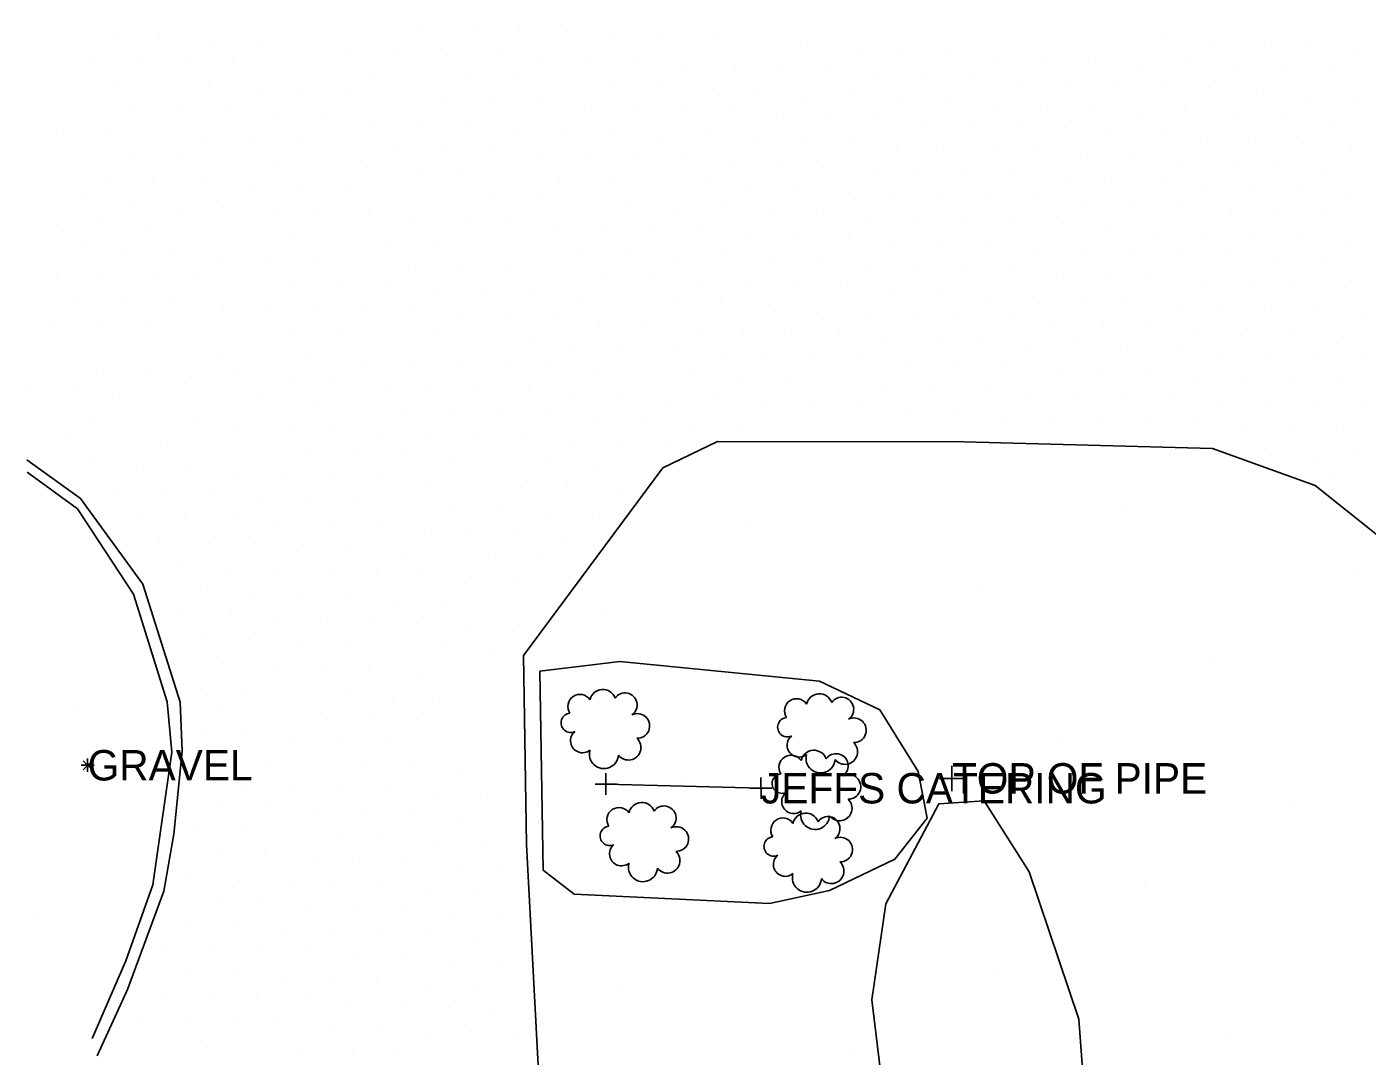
# Model space of a CAD drawing. Extents: x 1733582 to 1734070, y 467256 to 468256.
# Drawn here: x 1733724.1 to 1733803.5, y 467494.6 to 467555.6 of the extents above; entities that cross this region are included whole.
import ezdxf

# ---------------------------------------------------------------- set-up
doc = ezdxf.new("R2010")
doc.units = 0
for name, color, linetype in [('Default', 7, 'Continuous'), ('S_Curb_Type_3', 7, 'Continuous'), ('S_Drainage_Invert_Culvert', 7, 'Continuous'), ('S_Ground_SpotElevation', 7, 'Continuous'), ('S_Misc_MiscItems', 7, 'Continuous'), ('S_Property_Garden', 7, 'Continuous'), ('S_Roadway_Drive_Paved', 7, 'Continuous'), ('S_Survey_Shot', 7, 'Continuous'), ('S_Text', 7, 'Continuous'), ('S_Traffic_Sign_DoublePost', 7, 'Continuous'), ('S_Trees_Bush', 7, 'Continuous'), ('S_Trees_Bush_Line', 7, 'Continuous')]:
    doc.layers.add(name, color=color, linetype=linetype)

# ---------------------------------------------------------------- blocks, each defined once
blk = doc.blocks.new('POINT_DISPLAY')
at = {"layer": 'Default'}
blk.add_line((0, 0), (0, 0), dxfattribs=at)

msp = doc.modelspace()

# ---------------------------------------------------------------- linework, layer by layer
at = {"layer": 'S_Curb_Type_3'}
msp.add_lwpolyline([(1733724.139, 467529.217), (1733727.119, 467527.047), (1733730.432, 467522.001), (1733732.42, 467515.62), (1733732.714, 467512.654), (1733731.587, 467504.798), (1733729.979, 467500.29), (1733727.98, 467495.687)], dxfattribs=at)
at = {"layer": 'S_Drainage_Invert_Culvert'}
for p, q in [((1733778.9, 467511.846), (1733778.9, 467510.346)), ((1733778.15, 467511.096), (1733779.65, 467511.096))]:
    msp.add_line(p, q, dxfattribs=at)
at = {"layer": 'S_Misc_MiscItems'}
for p, q in [((1733727.982, 467511.608), (1733727.458, 467512.132)), ((1733727.982, 467512.132), (1733727.458, 467511.608)), ((1733727.72, 467512.263), (1733727.72, 467511.477)), ((1733728.113, 467511.87), (1733727.327, 467511.87))]:
    msp.add_line(p, q, dxfattribs=at)
at = {"layer": 'S_Property_Garden'}
msp.add_lwpolyline([(1733756.524, 467504.241), (1733754.694, 467505.659), (1733754.495, 467517.433), (1733759.233, 467518.012), (1733771.049, 467516.839), (1733774.623, 467515.157), (1733776.898, 467511.492), (1733777.426, 467508.736), (1733775.526, 467506.318), (1733771.64, 467504.466), (1733768.086, 467503.694), (1733756.524, 467504.241)], dxfattribs=at)
at = {"layer": 'S_Roadway_Drive_Paved'}
for points in [[(1733811.739, 467519.514), (1733806.075, 467523.904), (1733800.413, 467528.442), (1733794.32, 467530.63), (1733779.611, 467531.008), (1733765.012, 467531.03), (1733761.779, 467529.481), (1733753.522, 467518.374), (1733753.708, 467507.172), (1733754.671, 467488.867), (1733755.589, 467445.891), (1733749.43, 467445.76)], [(1733728.284, 467494.674), (1733730.081, 467498.603), (1733732.23, 467504.412), (1733732.833, 467507.798), (1733733.323, 467512.698), (1733733.207, 467515.602), (1733730.979, 467522.589), (1733727.293, 467527.659), (1733724.118, 467529.953)]]:
    msp.add_lwpolyline(points, dxfattribs=at)
at = {"layer": 'S_Survey_Shot'}
for p, q in [((1733758.408, 467510.123), (1733758.406, 467511.395)), ((1733757.771, 467510.758), (1733759.043, 467510.76)), ((1733758.407, 467510.759), (1733758.407, 467510.759)), ((1733766.956, 467510.509), (1733768.228, 467510.511)), ((1733767.593, 467509.874), (1733767.591, 467511.146)), ((1733767.592, 467510.51), (1733767.592, 467510.51))]:
    msp.add_line(p, q, dxfattribs=at)
at = {"layer": 'S_Traffic_Sign_DoublePost'}
msp.add_lwpolyline([(1733767.592, 467510.51), (1733758.407, 467510.759)], dxfattribs=at)
at = {"layer": 'S_Trees_Bush'}
for centre, radius, start, end in [((1733756.871, 467515.35), 0.716, 33.64054, 213.59091), ((1733758.224, 467515.585), 0.774, 19.72769, 168.00323), ((1733759.54, 467515.44), 0.714, 304.7168, 145.28321), ((1733771.05, 467515.328), 0.774, 19.72769, 168.00323), ((1733769.697, 467515.093), 0.716, 33.64054, 213.59091), ((1733772.366, 467515.183), 0.714, 304.7168, 145.28321), ((1733756.327, 467514.382), 0.575, 95.18751, 295.46148), ((1733760.267, 467514.196), 0.731, 268.12197, 116.01721), ((1733769.153, 467514.125), 0.575, 95.18751, 295.46148), ((1733773.093, 467513.939), 0.731, 268.12197, 116.01721), ((1733757.019, 467513.316), 0.705, 129.15555, 309.41051), ((1733759.743, 467512.92), 0.74, 216.98087, 47.49649), ((1733769.845, 467513.059), 0.705, 129.15555, 309.41051), ((1733772.569, 467512.663), 0.74, 216.98087, 47.49649), ((1733758.293, 467512.531), 0.861, 163.74266, 356.27601), ((1733769.372, 467511.751), 0.716, 33.64054, 213.59091), ((1733770.725, 467511.986), 0.774, 19.72769, 168.00323), ((1733771.119, 467512.274), 0.861, 163.74266, 356.27601), ((1733772.041, 467511.841), 0.714, 304.7168, 145.28321), ((1733768.828, 467510.783), 0.575, 95.18751, 295.46148), ((1733772.768, 467510.597), 0.731, 268.12197, 116.01721), ((1733760.534, 467508.891), 0.774, 19.72769, 168.00323), ((1733769.52, 467509.717), 0.705, 129.15555, 309.41051), ((1733772.244, 467509.321), 0.74, 216.98087, 47.49649), ((1733759.181, 467508.656), 0.716, 33.64054, 213.59091), ((1733761.85, 467508.746), 0.714, 304.7168, 145.28321), ((1733770.239, 467508.268), 0.774, 19.72769, 168.00323), ((1733770.794, 467508.932), 0.861, 163.74266, 356.27601), ((1733758.637, 467507.688), 0.575, 95.18751, 295.46148), ((1733762.577, 467507.502), 0.731, 268.12197, 116.01721), ((1733768.886, 467508.033), 0.716, 33.64054, 213.59091), ((1733771.555, 467508.123), 0.714, 304.7168, 145.28321), ((1733768.342, 467507.065), 0.575, 95.18751, 295.46148), ((1733772.282, 467506.879), 0.731, 268.12197, 116.01721), ((1733759.329, 467506.622), 0.705, 129.15555, 309.41051), ((1733762.053, 467506.226), 0.74, 216.98087, 47.49649), ((1733769.034, 467505.999), 0.705, 129.15555, 309.41051), ((1733760.603, 467505.837), 0.861, 163.74266, 356.27601), ((1733771.758, 467505.603), 0.74, 216.98087, 47.49649), ((1733770.308, 467505.214), 0.861, 163.74266, 356.27601)]:
    msp.add_arc(centre, radius, start, end, dxfattribs=at)
at = {"layer": 'S_Trees_Bush_Line'}
msp.add_lwpolyline([(1733757.132, 467425.823), (1733762.294, 467426.816), (1733768.302, 467429.336), (1733775.509, 467433.305), (1733779.429, 467440.16), (1733780.117, 467448.929), (1733774.149, 467497.977), (1733774.984, 467503.667), (1733778.123, 467509.595), (1733780.8, 467509.768), (1733783.475, 467505.563), (1733786.412, 467496.844), (1733790.523, 467441.256), (1733794.187, 467436.042), (1733797.957, 467433.37), (1733800.467, 467407.761), (1733803.443, 467377.812)], dxfattribs=at)

# ---------------------------------------------------------------- block references
at = {"layer": 'S_Ground_SpotElevation'}
for p in [(1733729.413, 467555.09), (1733747.567, 467555.559), (1733750.577, 467555.586), (1733753.304, 467555.377), (1733756.124, 467555.31), (1733758.919, 467555.005), (1733731.999, 467554.884), (1733734.853, 467554.669), (1733737.842, 467554.527), (1733743.246, 467554.324), (1733746.106, 467554.122), (1733761.739, 467554.845), (1733764.785, 467554.842), (1733770.328, 467554.514), (1733773.263, 467554.191), (1733791.441, 467554.845), (1733794.262, 467554.612), (1733797.376, 467554.538), (1733800.106, 467554.378), (1733802.952, 467554.242), (1733727.938, 467553.829), (1733730.657, 467553.441), (1733733.579, 467553.536), (1733736.271, 467553.445), (1733749.044, 467553.904), (1733751.977, 467553.884), (1733754.653, 467553.667), (1733757.443, 467553.684), (1733760.254, 467553.489), (1733763.19, 467553.312), (1733775.911, 467554.035), (1733778.646, 467554.085), (1733781.617, 467553.798), (1733784.393, 467553.843), (1733787.393, 467553.6), (1733789.964, 467553.37), (1733792.854, 467553.469), (1733744.693, 467552.724), (1733750.441, 467552.762), (1733753.237, 467552.576), (1733766.065, 467553.289), (1733768.69, 467553.224), (1733771.62, 467553.077), (1733774.355, 467552.905), (1733777.403, 467552.883), (1733780.087, 467552.574), (1733795.657, 467553.143), (1733798.402, 467553.049), (1733801.234, 467552.913), (1733729.171, 467552.277), (1733734.879, 467552.043), (1733758.928, 467552.054), (1733761.54, 467552.097), (1733764.713, 467551.961), (1733767.472, 467551.848), (1733782.905, 467552.322), (1733785.907, 467552.25), (1733788.597, 467552.198), (1733791.455, 467552.177), (1733794.116, 467551.966), (1733796.945, 467551.737), (1733737.699, 467551.649), (1733740.38, 467551.671), (1733743.236, 467551.5), (1733748.75, 467551.262), (1733751.744, 467551.079), (1733754.591, 467551.072), (1733770.182, 467551.446), (1733772.859, 467551.541), (1733775.691, 467551.429), (1733778.54, 467551.17), (1733781.6, 467550.953), (1733799.868, 467551.425), (1733802.69, 467551.288), (1733730.374, 467550.793), (1733733.252, 467550.692), (1733736.036, 467550.559), (1733738.815, 467550.332), (1733741.942, 467550.218), (1733757.574, 467550.78), (1733760.321, 467550.646), (1733762.96, 467550.595), (1733765.841, 467550.625), (1733768.528, 467550.331), (1733771.403, 467550.191), (1733774.283, 467550.123), (1733784.164, 467550.809), (1733787.077, 467550.828), (1733789.947, 467550.487), (1733792.665, 467550.638), (1733795.768, 467550.437), (1733798.579, 467550.308), (1733726.306, 467549.413), (1733728.868, 467549.374), (1733744.519, 467549.914), (1733747.416, 467550.027), (1733750.091, 467549.881), (1733753.008, 467549.481), (1733755.958, 467549.334), (1733777.183, 467549.777), (1733779.993, 467549.866), (1733782.772, 467549.684), (1733785.537, 467549.602), (1733791.283, 467549.363), (1733801.311, 467550.038), (1733734.513, 467549.042), (1733737.32, 467549.112), (1733740.221, 467548.985), (1733758.7, 467549.304), (1733761.665, 467549.081), (1733764.36, 467549.285), (1733767.156, 467548.984), (1733770.184, 467548.852), (1733772.81, 467548.788), (1733775.624, 467548.582), (1733788.311, 467549.306), (1733794.021, 467548.898), (1733796.881, 467548.827), (1733799.728, 467548.65), (1733802.556, 467548.575), (1733730.468, 467547.779), (1733733.041, 467547.901), (1733745.875, 467548.442), (1733748.902, 467548.371), (1733751.532, 467548.395), (1733754.36, 467548.023), (1733757.345, 467547.918), (1733759.989, 467547.876), (1733778.393, 467548.359), (1733781.301, 467548.317), (1733784.004, 467548.201), (1733786.899, 467547.894), (1733789.67, 467547.773), (1733738.831, 467547.416), (1733744.3, 467547.255), (1733747.374, 467547.031), (1733762.96, 467547.716), (1733765.809, 467547.669), (1733768.481, 467547.386), (1733771.271, 467547.256), (1733774.246, 467547.105), (1733776.933, 467547.002), (1733792.461, 467547.649), (1733795.541, 467547.427), (1733798.112, 467547.386), (1733801.039, 467547.212), (1733728.766, 467546.466), (1733731.549, 467546.351), (1733734.494, 467546.333), (1733740.229, 467546.216), (1733749.962, 467546.906), (1733755.686, 467546.64), (1733758.715, 467546.667), (1733764.225, 467546.43), (1733779.71, 467546.836), (1733782.582, 467546.938), (1733785.639, 467546.699), (1733788.361, 467546.548), (1733791.341, 467546.386), (1733793.809, 467546.233), (1733727.389, 467545.426), (1733737.427, 467546.138), (1733743.06, 467545.982), (1733751.544, 467545.671), (1733754.371, 467545.51), (1733766.99, 467546.021), (1733769.747, 467545.878), (1733772.749, 467545.799), (1733775.366, 467545.74), (1733778.243, 467545.708), (1733781.206, 467545.561), (1733784.072, 467545.454), (1733796.751, 467545.99), (1733799.706, 467545.965), (1733802.358, 467545.685), (1733730.409, 467545.109), (1733733.11, 467544.823), (1733735.786, 467544.888), (1733738.819, 467544.684), (1733759.906, 467545.188), (1733762.608, 467544.817), (1733765.499, 467544.93), (1733768.4, 467544.807), (1733771.31, 467544.6), (1733786.828, 467545.041), (1733789.549, 467544.966), (1733792.39, 467545.008), (1733795.425, 467544.759), (1733797.963, 467544.587), (1733725.857, 467543.884), (1733728.619, 467543.918), (1733741.419, 467544.391), (1733744.332, 467544.491), (1733747.046, 467544.304), (1733750.13, 467544.216), (1733752.634, 467543.922), (1733755.591, 467543.835), (1733774.141, 467544.251), (1733776.75, 467544.328), (1733779.653, 467544.156), (1733782.437, 467543.982), (1733785.497, 467543.915), (1733800.811, 467544.452), (1733731.406, 467543.566), (1733739.909, 467543.167), (1733758.354, 467543.614), (1733761.142, 467543.462), (1733764.12, 467543.521), (1733766.752, 467543.245), (1733769.789, 467543.049), (1733772.763, 467543.083), (1733788.314, 467543.613), (1733790.956, 467543.435), (1733793.915, 467543.385), (1733796.767, 467543.246), (1733799.411, 467542.99), (1733727.387, 467542.566), (1733730.035, 467542.239), (1733732.822, 467542.212), (1733745.677, 467542.819), (1733748.535, 467542.629), (1733756.892, 467542.259), (1733775.524, 467542.835), (1733778.115, 467542.639), (1733781.013, 467542.515), (1733784.013, 467542.35), (1733786.794, 467542.197), (1733792.248, 467542.213), (1733802.282, 467542.82), (1733735.696, 467542.012), (1733738.482, 467541.701), (1733741.392, 467541.592), (1733759.862, 467542.089), (1733762.535, 467541.981), (1733765.288, 467542.039), (1733768.229, 467541.896), (1733770.925, 467541.7), (1733773.881, 467541.502), (1733789.553, 467542.112), (1733795.275, 467542.021), (1733797.969, 467541.817), (1733800.836, 467541.646), (1733725.884, 467540.999), (1733728.537, 467540.994), (1733731.533, 467540.75), (1733734.156, 467540.758), (1733747.128, 467541.33), (1733749.93, 467541.353), (1733752.7, 467541.314), (1733758.385, 467540.81), (1733760.974, 467540.805), (1733776.782, 467541.28), (1733779.634, 467541.308), (1733782.469, 467541.237), (1733785.085, 467540.859), (1733788.114, 467540.777), (1733790.732, 467540.769), (1733739.877, 467540.509), (1733742.807, 467540.429), (1733745.634, 467540.207), (1733748.263, 467539.832), (1733751.217, 467539.934), (1733763.986, 467540.423), (1733766.744, 467540.544), (1733769.545, 467540.22), (1733772.326, 467540.353), (1733775.305, 467539.987), (1733778.062, 467539.849), (1733793.676, 467540.523), (1733796.566, 467540.346), (1733799.2, 467540.333), (1733802.155, 467540.18), (1733727.179, 467539.595), (1733729.917, 467539.44), (1733732.807, 467539.294), (1733735.746, 467539.099), (1733738.286, 467539.042), (1733753.895, 467539.701), (1733756.71, 467539.496), (1733762.426, 467539.299), (1733765.197, 467539.278), (1733768.017, 467539.128), (1733780.974, 467539.649), (1733783.656, 467539.603), (1733786.595, 467539.377), (1733789.315, 467539.344), (1733792.242, 467539.164), (1733794.853, 467539.076), (1733741.244, 467538.87), (1733744.08, 467538.897), (1733746.814, 467538.726), (1733749.642, 467538.627), (1733752.555, 467538.264), (1733755.362, 467538.233), (1733770.887, 467538.689), (1733773.774, 467538.673), (1733776.735, 467538.562), (1733779.283, 467538.425), (1733782.412, 467538.234), (1733797.847, 467538.895), (1733800.581, 467538.741), (1733803.417, 467538.623), (1733725.77, 467538.165), (1733728.294, 467538.109), (1733731.316, 467538.13), (1733758.046, 467538.12), (1733760.888, 467538.082), (1733763.875, 467537.634), (1733766.532, 467537.653), (1733769.413, 467537.532), (1733784.924, 467538.183), (1733787.866, 467537.871), (1733790.59, 467537.974), (1733793.43, 467537.739), (1733796.422, 467537.72), (1733799.236, 467537.621), (1733739.799, 467537.415), (1733742.725, 467537.367), (1733748.251, 467537.339), (1733753.908, 467537.005), (1733756.628, 467536.669), (1733759.448, 467536.67), (1733762.362, 467536.647), (1733772.251, 467537.393), (1733775.013, 467537.145), (1733778.026, 467536.941), (1733780.71, 467536.99), (1733783.45, 467536.798), (1733786.396, 467536.85), (1733802.112, 467537.242), (1733735.493, 467536.2), (1733740.96, 467536.022), (1733765.168, 467536.206), (1733767.829, 467536.172), (1733770.703, 467536.03), (1733773.544, 467535.94), (1733789.278, 467536.524), (1733792.227, 467536.431), (1733794.786, 467536.157), (1733797.782, 467535.929), (1733800.418, 467536.005), (1733803.329, 467535.876), (1733728.224, 467535.17), (1733731.067, 467535.223), (1733743.967, 467535.804), (1733746.811, 467535.709), (1733749.616, 467535.537), (1733752.478, 467535.412), (1733755.146, 467535.478), (1733757.978, 467535.118), (1733776.393, 467535.738), (1733779.211, 467535.496), (1733781.995, 467535.591), (1733785.136, 467535.38), (1733787.816, 467535.24), (1733790.433, 467535.123), (1733733.863, 467534.876), (1733736.726, 467535.037), (1733739.648, 467534.688), (1733742.312, 467534.634), (1733745.285, 467534.272), (1733748.026, 467534.375), (1733750.807, 467534.308), (1733763.649, 467535.039), (1733766.402, 467534.679), (1733769.183, 467534.78), (1733774.834, 467534.372), (1733777.805, 467534.264), (1733793.309, 467534.817), (1733796.216, 467534.829), (1733799.129, 467534.753), (1733801.941, 467534.564), (1733724.163, 467534.043), (1733726.966, 467534.1), (1733729.582, 467533.687), (1733738.001, 467533.523), (1733753.824, 467534.065), (1733756.412, 467533.86), (1733759.258, 467533.755), (1733764.848, 467533.534), (1733780.827, 467534.097), (1733783.431, 467533.966), (1733786.378, 467533.925), (1733789.062, 467533.663), (1733791.942, 467533.653), (1733794.61, 467533.468), (1733741.032, 467533.163), (1733746.472, 467532.978), (1733749.359, 467532.912), (1733752.17, 467532.837), (1733762.133, 467533.452), (1733767.844, 467533.233), (1733770.693, 467533.074), (1733773.355, 467533.122), (1733776.304, 467532.994), (1733779.201, 467532.915), (1733797.554, 467533.456), (1733800.454, 467533.17), (1733803.298, 467533.14), (1733728.034, 467532.495), (1733733.9, 467532.242), (1733736.573, 467531.896), (1733739.67, 467531.92), (1733755.031, 467532.615), (1733757.921, 467532.328), (1733760.683, 467532.225), (1733763.455, 467532.063), (1733766.433, 467532.041), (1733782.004, 467532.512), (1733784.843, 467532.475), (1733787.639, 467532.462), (1733790.376, 467532.085), (1733793.2, 467532.095), (1733796.032, 467532.018), (1733799.016, 467531.968), (1733726.704, 467531.127), (1733742.146, 467531.846), (1733745.183, 467531.576), (1733747.955, 467531.358), (1733750.782, 467531.416), (1733753.576, 467531.153), (1733801.653, 467531.779), (1733732.474, 467530.862), (1733740.925, 467530.391), (1733746.449, 467530.296), (1733756.366, 467530.989), (1733759.403, 467530.993), (1733762.26, 467530.834), (1733797.426, 467530.624), (1733727.974, 467529.777), (1733733.67, 467529.501), (1733743.627, 467530.265), (1733749.371, 467530.083), (1733755.063, 467529.795), (1733757.825, 467529.677), (1733800.287, 467530.138), (1733802.96, 467530.264), (1733731.014, 467529.486), (1733736.502, 467529.173), (1733739.21, 467529.016), (1733742.204, 467528.826), (1733744.916, 467528.807), (1733801.572, 467528.923), (1733729.39, 467527.981), (1733732.21, 467528.22), (1733735.028, 467527.907), (1733747.802, 467528.533), (1733753.358, 467528.339), (1733756.159, 467528.382), (1733759.134, 467527.98), (1733737.721, 467527.668), (1733740.55, 467527.508), (1733743.515, 467527.645), (1733730.673, 467526.691), (1733733.439, 467526.461), (1733736.41, 467526.509), (1733749.236, 467527.01), (1733752.085, 467526.913), (1733754.848, 467526.745), (1733757.642, 467526.666), (1733789.292, 467527.025), (1733739.065, 467526.262), (1733741.998, 467526.079), (1733744.973, 467526.037), (1733747.667, 467525.704), (1733750.391, 467525.618), (1733753.146, 467525.614), (1733766.954, 467526.032), (1733731.968, 467525.367), (1733734.88, 467525.028), (1733737.665, 467524.995), (1733740.494, 467524.927), (1733755.999, 467525.433), (1733743.173, 467524.657), (1733746.279, 467524.477), (1733751.856, 467524.206), (1733754.67, 467524.108), (1733733.281, 467523.799), (1733736.057, 467523.53), (1733739.068, 467523.397), (1733742.014, 467523.181), (1733744.818, 467523.144), (1733747.558, 467523.173), (1733802.894, 467523.153), (1733750.466, 467523.054), (1733753.093, 467522.799), (1733734.79, 467522.334), (1733737.56, 467522.031), (1733740.485, 467521.821), (1733743.186, 467521.923), (1733780.556, 467522.16), (1733733.334, 467520.944), (1733736.223, 467520.796), (1733746.122, 467521.508), (1733748.903, 467521.394), (1733758.217, 467521.167), (1733739.029, 467520.549), (1733741.929, 467520.481), (1733744.537, 467520.242), (1733747.21, 467520.272), (1733750.248, 467520.123), (1733734.439, 467519.404), (1733737.247, 467519.33), (1733752.892, 467519.801), (1733740.25, 467519.009), (1733743.003, 467519.009), (1733748.686, 467518.867), (1733751.741, 467518.515), (1733735.768, 467517.867), (1733738.914, 467517.843), (1733741.554, 467517.717), (1733794.158, 467518.288), (1733744.371, 467517.482), (1733747.227, 467517.25), (1733734.377, 467516.438), (1733737.183, 467516.309), (1733742.937, 467516.143), (1733727.142, 467515.309), (1733745.78, 467515.861), (1733748.55, 467515.709), (1733735.742, 467515.193), (1733741.519, 467514.977), (1733744.453, 467514.591), (1733747.205, 467514.593), (1733734.466, 467513.703), (1733737.105, 467513.608), (1733739.902, 467513.578), (1733742.782, 467513.265), (1733745.657, 467513.142), (1733785.421, 467513.423), (1733735.496, 467512.361), (1733738.522, 467512.087), (1733744.175, 467511.9), (1733746.972, 467511.721), (1733749.928, 467511.706), (1733734.23, 467511.057), (1733736.999, 467510.626), (1733739.694, 467510.615), (1733742.572, 467510.663), (1733745.368, 467510.453), (1733763.009, 467511.209), (1733748.464, 467510.22), (1733750.958, 467510.048), (1733735.432, 467509.609), (1733738.472, 467509.444), (1733741.124, 467509.054), (1733744.196, 467509.001), (1733747, 467509.011), (1733799.023, 467509.552), (1733734.025, 467508.188), (1733749.543, 467508.728), (1733736.973, 467508.038), (1733742.578, 467507.733), (1733745.206, 467507.448), (1733748.173, 467507.328), (1733751.124, 467507.342), (1733735.559, 467506.544), (1733738.213, 467506.59), (1733741.229, 467506.281), (1733743.827, 467506.208), (1733746.556, 467506.206), (1733749.686, 467505.973), (1733752.196, 467505.773), (1733733.777, 467505.337), (1733736.695, 467505.05), (1733739.723, 467504.942), (1733742.387, 467504.727), (1733745.046, 467504.684), (1733747.983, 467504.423), (1733750.72, 467504.377), (1733790.286, 467504.687), (1733735.438, 467503.769), (1733738.041, 467503.658), (1733740.94, 467503.413), (1733746.617, 467503.303), (1733724.529, 467503.107), (1733743.565, 467503.285), (1733749.356, 467503.033), (1733752.209, 467502.787), (1733733.838, 467502.293), (1733736.725, 467502.407), (1733739.489, 467502.112), (1733742.315, 467501.976), (1733745.208, 467501.929), (1733747.772, 467501.811), (1733732.197, 467500.948), (1733735.232, 467500.988), (1733750.774, 467501.536), (1733737.971, 467500.829), (1733740.801, 467500.901), (1733743.507, 467500.519), (1733746.611, 467500.381), (1733749.268, 467500.213), (1733733.772, 467499.7), (1733736.637, 467499.452), (1733752.218, 467500.09), (1733781.549, 467499.822), (1733739.224, 467499.189), (1733742.046, 467499.169), (1733744.837, 467498.989), (1733747.862, 467498.829), (1733750.66, 467498.651), (1733759.21, 467498.828), (1733732.214, 467498.184), (1733734.984, 467498.009), (1733737.737, 467498.043), (1733740.635, 467497.979), (1733743.307, 467497.642), (1733746.403, 467497.683), (1733749.094, 467497.539), (1733751.868, 467497.331), (1733730.753, 467496.834), (1733733.513, 467496.831), (1733736.443, 467496.586), (1733738.98, 467496.576), (1733742.041, 467496.428), (1733744.878, 467496.124), (1733747.78, 467496.038), (1733750.434, 467496.107), (1733753.256, 467495.742), (1733795.151, 467495.95), (1733734.831, 467495.167), (1733740.404, 467494.9), (1733743.425, 467494.768), (1733746.141, 467494.712), (1733772.812, 467494.957)]:
    msp.add_blockref('POINT_DISPLAY', p, dxfattribs=at)

# ---------------------------------------------------------------- texts
at = {"layer": 'S_Text'}
for s, p in [('GRAVEL', (1733727.72, 467510.97)), ('JEFFS CATERING', (1733767.592, 467509.61)), ('TOP OF PIPE', (1733778.9, 467510.196))]:
    msp.add_text(s, height=1.8, dxfattribs=at).set_placement(p)

doc.saveas('drawing.dxf')
